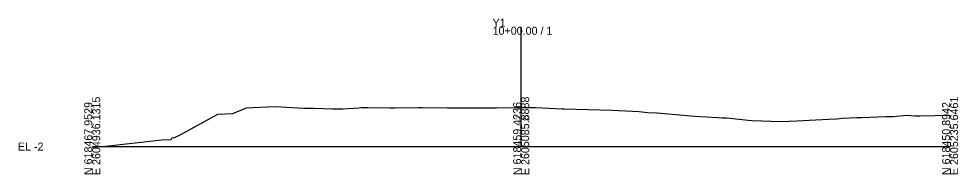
# Model space of a CAD drawing. Extents: x -26 to 1603, y -10 to 2541.
# Drawn here: x -25.7 to 302.8, y -9.7 to 44.8 of the extents above; entities that cross this region are included whole.
import ezdxf

# ---------------------------------------------------------------- set-up
doc = ezdxf.new("R2010")
doc.units = 0
for name, color, linetype in [('Default', 7, 'Continuous'), ('Exist Cross Section Cell', 7, 'Continuous'), ('Exist XS Center Line Elevation Label', 7, 'Continuous'), ('Exist XS Ground Line', 7, 'Continuous')]:
    doc.layers.add(name, color=color, linetype=linetype)

msp = doc.modelspace()

# ---------------------------------------------------------------- linework, layer by layer
at = {"layer": 'Exist Cross Section Cell'}
for p, q in [((150, 0), (150, 41.96)), ((0, 0), (150, 0)), ((150, 0), (300, 0))]:
    msp.add_line(p, q, dxfattribs=at)
at = {"layer": 'Exist XS Ground Line'}
msp.add_lwpolyline([(0, -0.23), (3.56, -0.03), (24.33, 2.31), (27.65, 2.48), (28, 3.18), (28.48, 3.02), (30.99, 4.27), (43.94, 11.35), (49.11, 11.55), (53.96, 13.54), (58.58, 13.79), (63.97, 13.99), (68.06, 13.74), (73.99, 13.5), (77.54, 13.41), (84, 13.21), (87.58, 13.17), (93.3, 13.51), (94.02, 13.64), (96.49, 13.71), (104.04, 13.58), (105.97, 13.57), (114.05, 13.68), (115.44, 13.69), (124.07, 13.56), (124.92, 13.56), (126.64, 13.55), (135.64, 13.58), (141.41, 13.57), (150, 13.63), (153.85, 13.66), (154.98, 13.64), (164.2, 13.24), (165.03, 13.26), (181.78, 12.74), (184.17, 12.65), (191.26, 12.23), (194.18, 11.97), (197.46, 11.81), (204.2, 11.25), (208.08, 10.87), (210.7, 10.59), (218.84, 10.21), (220.33, 10.11), (221.96, 10.06), (229.4, 9.25), (230.82, 9.12), (240.83, 8.72), (246.38, 8.98), (250.66, 9.2), (257.61, 9.61), (260.43, 9.72), (262.24, 9.89), (267.36, 10.14), (269.16, 10.21), (277.55, 10.48), (278.85, 10.52), (279.31, 10.53), (279.67, 10.54), (279.98, 10.55), (285.04, 10.95), (287.83, 10.78), (289.05, 10.8), (289.41, 10.8), (300, 10.97)], dxfattribs=at)

# ---------------------------------------------------------------- texts
at = {"layer": 'Default'}
msp.add_text('-', height=0.0001, dxfattribs=at).set_placement((0, 0))
at = {"layer": 'Exist Cross Section Cell'}
for s, p in [('Y1', (140, 41.96)), ('10+00.00 / 1', (140, 39.16)), ('EL -2', (-26, -1.4))]:
    msp.add_text(s, height=2.8, dxfattribs=at).set_placement(p)
for s, p in [('E 2604936.1315', (2.8, -10)), ('E 2605085.8888', (152.8, -10)), ('E 2605235.6461', (302.8, -10)), ('N 618467.9529', (0, -10)), ('N 618459.4236', (150, -10)), ('N 618450.8942', (300, -10))]:
    msp.add_text(s, height=2.8, rotation=90, dxfattribs=at).set_placement(p)
at = {"layer": 'Exist XS Center Line Elevation Label'}
msp.add_text('11.63', height=1.5, dxfattribs=at).set_placement((147.77, 9.13))

doc.saveas('drawing.dxf')
